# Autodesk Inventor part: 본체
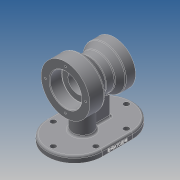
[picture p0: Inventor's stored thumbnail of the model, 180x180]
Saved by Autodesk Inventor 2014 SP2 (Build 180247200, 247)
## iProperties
Created: 2020-01
Part Number: 본체
Material: Generic
Document SubType Name: Modeling
Designer: kb542-10
Density: 1 g/cm^3
Appearance: Default
Author: kb542-10
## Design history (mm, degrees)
sketch "스케치1"
  geometry: L1 (0, 0)-(0, -80); L2 (0, -80)-(35, -80); L3 (35, -80)-(35, -64); L4 (35, -64)-(27.5, -53.289); L5 (27.5, -53.289)-(27.5, -38.897); L6 (27.5, -38.897)-(40, -24); L7 (40, -24)-(40, 0); L8 (40, 0)-(0, 0); L9 (26, 0)-(26, -20); L10 (26, -20)-(16, -20); L11 (16, -20)-(16, -63); L12 (16, -63)-(20, -63); L13 (20, -63)-(20, -80)
  constraints: 26 end point, 6 parallel, 4 perpendicular, 2 point on line, 1 vertical
  dimensions: "d7" = 80 diameter of L7 L1; "d8" = 80 distance between parallel lines of L2 L8; "d9" = 40 deg angle of L6 L5; "d10" = 35 deg angle of L4 L5; "d11" = 16 distance of L2.end L3.end; "d12" = 24 distance of L6.end L7.end; "d13" = 70 diameter of L3 L1; "d14" = 55 diameter of L5 L1; "d15" = 52 diameter of L9 L1; "d16" = 40 diameter of L13 L1; "d17" = 32 diameter of L11 L1; "d18" = 17 distance between parallel lines of L2 L12; "d19" = 20 distance between parallel lines of L8 L10
revolve "회전1" sketch "스케치1" stored, may be unused: angle "d20" = 90 deg
node "작업 평면1"
sketch "스케치2"
  geometry: L1 (25.134, 0)-(-20.586, 0); L2 (0, 30)-(0, -110); L3 (45, -15)-(45, -65); L4 (-45, -65)-(-45, -15); A1 r 45 centre (0, -15) between (45, -15) and (-45, -15); A2 r 45 centre (0, -65) between (-45, -65) and (45, -65); 2 further points
  constraints: 10 end point, 6 point on circle, 4 tangent, 3 point on line, 2 centre point, 2 vertical alignment, 1 horizontal, 1 midpoint, 1 parallel
  dimensions: "d23" = 50 distance of A2.centre A1.centre; "d24" = 45 radius of A1; "d25" = 30 distance of point (0, 0) L2.start
extrude "돌출1" join sketch "스케치2" distance "d26" = 10; taper "d27" = 0 deg
sketch "스케치4"
  geometry: L1 (-45, 65)-(-45, 15) reference; L2 (45, 15)-(45, 65) reference; L3 (-35, 15)-(-35, 65); L4 (35, 65)-(35, 15); C1 r 4.5 at (-35, 15); C2 r 4.5 at (-35, 65); C3 r 4.5 at (0, -20); C4 r 4.5 at (35, 15); C5 r 4.5 at (35, 65); C6 r 4.5 at (0, 100); A1 r 45 centre (0, 15) between (-45, 15) and (45, 15) reference; A2 r 45 centre (0, 65) between (45, 65) and (-45, 65) reference; A3 r 35 centre (0, 65) between (35, 65) and (-35, 65); A4 r 35 centre (0, 15) between (-35, 15) and (35, 15); 1 further point
  constraints: 8 centre point, 6 point on circle, 4 coincident, 4 end point, 3 other
  dimensions: "d31" = 10 distance between parallel lines of L2 L4; "d32" = 9 diameter of C1; "d33" = 9 diameter of C3; "d34" = 9 diameter of C2; "d35" = 9 diameter of C6; "d36" = 9 diameter of C5; "d37" = 9 diameter of C4
extrude "돌출2" cut sketch "스케치4" stored distance "d38" = 10; taper "d39" = 0 deg
sketch "스케치5"
  geometry: L1 (5, 43.199)-(-5, 43.199); L2 (-5, 43.199)-(-5, 70); L3 (-5, 70)-(5, 70); L4 (5, 70)-(5, 43.199); L5 (0, 70)-(0, 74.923); L6 (0, -30)-(0, -40.513); A1 r 45 centre (0, 15) between (-45, 15) and (45, 15) reference; A2 r 16 centre (0, 28) between (5, 43.199) and (-5, 43.199); 1 further point
  constraints: 12 end point, 3 parallel, 3 point on circle, 1 centre point, 1 collinear, 1 horizontal, 1 midpoint, 1 perpendicular, 1 vertical alignment
  dimensions: "d40" = 10 distance between parallel lines of L2 L4; "d41" = 32 diameter of A2; "d42" = 58 distance of A2.centre L6.start; "d43" = 100 distance of L5.start L6.start
extrude "돌출3" join sketch "스케치5" stored distance "d44" = 10; taper "d45" = 0 deg
sketch "스케치6" dims "d46" = 66
  geometry: C1 r 26 at (0, 0) reference; C2 r 40 at (0, 0) reference; 5 further points
  constraints: 2 vertical alignment, 1 coincident, 7 other
  dimensions: "d49" = 360 deg dimension on C1.centre point (0, 33) (derived)
hole "구멍1" sketch "스케치6" at (0, 33), (-33, 0), (0, -33), (33, 0) diameter "d51" = 3.242; stored, may be unused: countersink angle "d55" = 90 deg, drill point angle "d57" = 118 deg; dims "d52" = 9, "d53" = 4, "d54" = 2, "d56" = 11
sketch "스케치7" dims "d58" = 55
  geometry: C1 r 20 at (0, 0) reference; A1 r 35 centre (0, 0) between (-5, -34.641) and (5, -34.641) reference; 5 further points
  constraints: 2 vertical alignment, 1 coincident, 7 other
  dimensions: "d61" = 360 deg dimension on A1.centre point (0, 27.5) (derived)
hole "구멍2" sketch "스케치7" at (0, 27.5), (-27.5, 0), (0, -27.5), (27.5, 0) diameter "d63" = 3.242; stored, may be unused: countersink angle "d67" = 90 deg, drill point angle "d69" = 118 deg; dims "d64" = 9, "d65" = 4, "d66" = 2, "d68" = 11
chamfer "모따기1" distance "d70" = 1; stored, may be unused: second distance "d71" = 2, angle "d72" = 45 deg
chamfer "모따기2" distance "d73" = 1; stored, may be unused: second distance "d74" = 2, angle "d75" = 45 deg
fillet "모깎기1" dims "d76" = 3, "d77" = 0.3
sketch "스케치8"
  geometry: L1 (50, 0)-(95, 0) reference; L2 (0, 7)-(0, 7) reference; L3 (0, 0)-(0, 7) reference; L4 (0, 0)-(0, 0) reference; L5 (0, 0)-(0, 7) reference; L6 (-45, 0)-(-45, 7) reference; 2 further points
  constraints: 1 other
  dimensions: "d78" = 4 distance from line of L1 point (25, 4); "d79" = 70 distance from line of point (25, 4) L6
feature "엠보싱1" sketch "스케치8" dims "d7" = 80, "d8" = 80, "d9" = 40 deg, "d10" = 35 deg, "d11" = 16, "d12" = 24, "d13" = 70, "d14" = 55, "d15" = 52, "d16" = 40, "d17" = 32, "d18" = 17, "d19" = 20, "d23" = 50, "d24" = 45, "d25" = 30, "d80" = 0.5, "d81" = 0
node "솔리드1"
node "투영된 루프1"
